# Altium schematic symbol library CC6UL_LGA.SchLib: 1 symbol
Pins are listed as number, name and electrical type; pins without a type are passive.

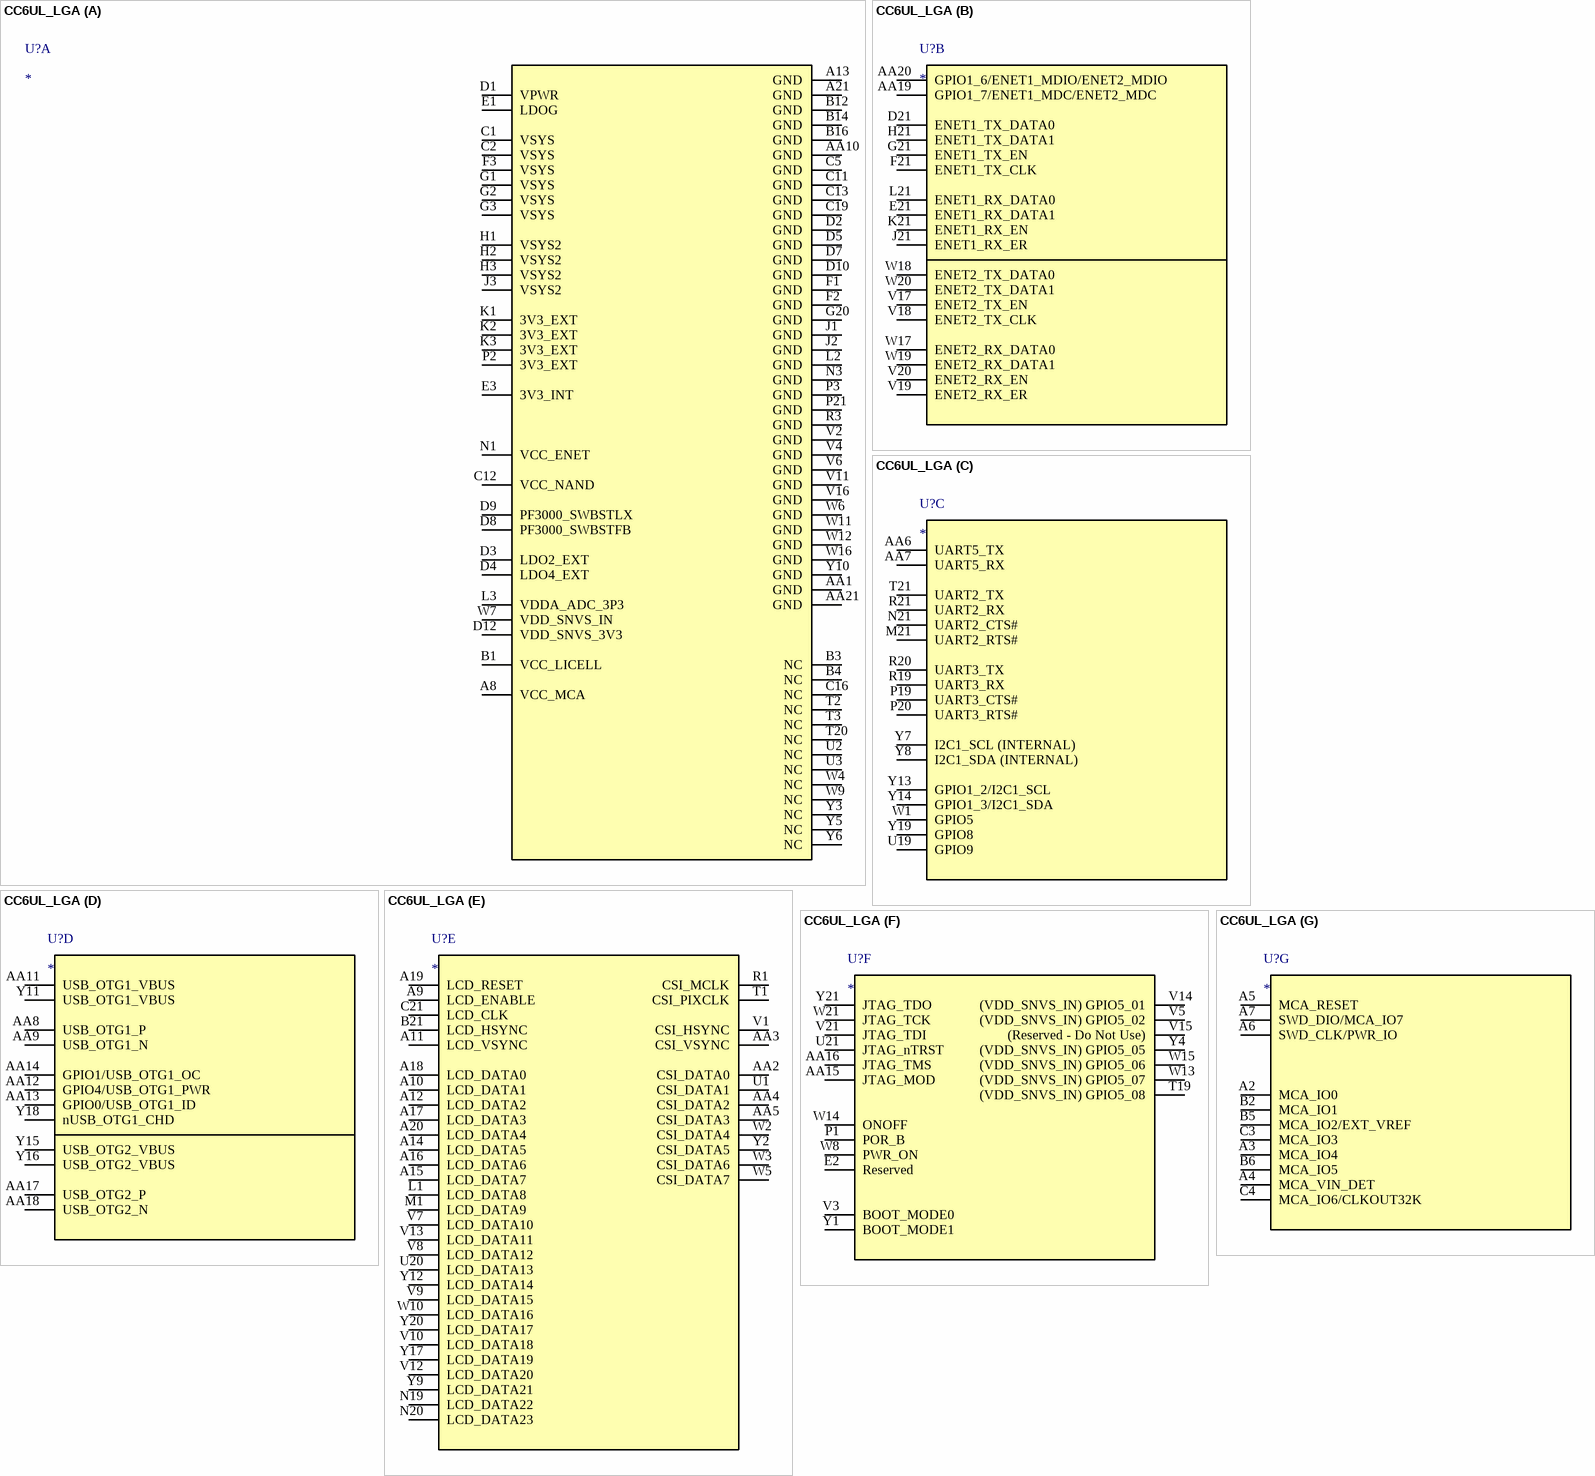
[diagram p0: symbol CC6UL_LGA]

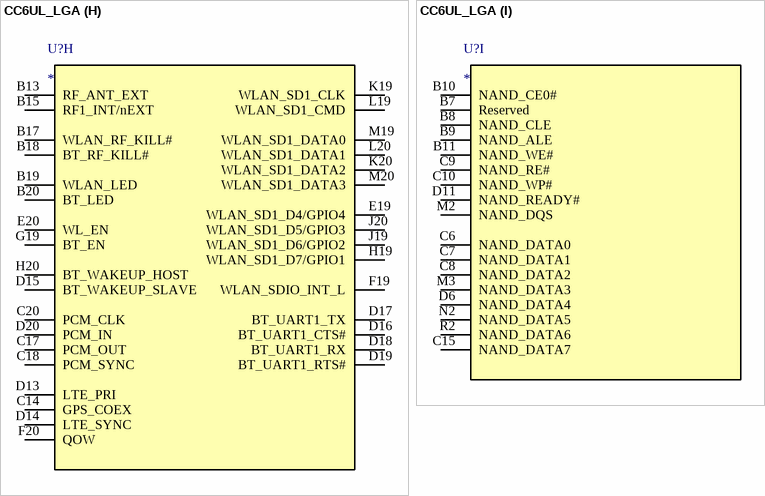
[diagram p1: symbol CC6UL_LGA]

## CC6UL_LGA
designator U?
CC6UL LGA
part A pins: A8 VCC_MCA (power), A13 GND (power), A21 GND, AA1 GND, AA10 GND (power), AA21 GND, B1 VCC_LICELL, B3 NC, B4 NC, B12 GND, B14 GND, B16 GND, C1 VSYS, C2 VSYS, C5 GND, C11 GND, C12 VCC_NAND, C13 GND, C16 NC, C19 GND, D1 VPWR, D2 GND, D3 LDO2_EXT, D4 LDO4_EXT, D5 GND, D7 GND, D8 PF3000_SWBSTFB, D9 PF3000_SWBSTLX, D10 GND, D12 VDD_SNVS_3V3, E1 LDOG, E3 3V3_INT, F1 GND (power), F2 GND, F3 VSYS, G1 VSYS (power), G2 VSYS, G3 VSYS, G20 GND, H1 VSYS2 (power), H2 VSYS2, H3 VSYS2, J1 GND (power), J2 GND, J3 VSYS2, K1 3V3_EXT (power), K2 3V3_EXT, K3 3V3_EXT, L2 GND, L3 VDDA_ADC_3P3, N1 VCC_ENET (power), N3 GND, P2 3V3_EXT, P3 GND, P21 GND, R3 GND, T2 NC, T3 NC, T20 NC, U2 NC, U3 NC, V2 GND, V4 GND, V6 GND, V11 GND, V16 GND, W4 NC, W6 GND, W7 VDD_SNVS_IN, W9 NC, W11 GND, W12 GND, W16 GND, Y3 NC, Y5 NC, Y6 NC, Y10 GND
part B pins: AA19 GPIO1_7/ENET1_MDC/ENET2_MDC, AA20 GPIO1_6/ENET1_MDIO/ENET2_MDIO, D21 ENET1_TX_DATA0, E21 ENET1_RX_DATA1, F21 ENET1_TX_CLK, G21 ENET1_TX_EN, H21 ENET1_TX_DATA1, J21 ENET1_RX_ER, K21 ENET1_RX_EN, L21 ENET1_RX_DATA0, V17 ENET2_TX_EN, V18 ENET2_TX_CLK, V19 ENET2_RX_ER, V20 ENET2_RX_EN, W17 ENET2_RX_DATA0, W18 ENET2_TX_DATA0, W19 ENET2_RX_DATA1, W20 ENET2_TX_DATA1
part C pins: AA6 UART5_TX, AA7 UART5_RX, M21 UART2_RTS#, N21 UART2_CTS#, P19 UART3_CTS#, P20 UART3_RTS#, R19 UART3_RX, R20 UART3_TX, R21 UART2_RX, T21 UART2_TX, U19 GPIO9, W1 GPIO5, Y7 I2C1_SCL (INTERNAL), Y8 I2C1_SDA (INTERNAL), Y13 GPIO1_2/I2C1_SCL, Y14 GPIO1_3/I2C1_SDA, Y19 GPIO8
part D pins: AA8 USB_OTG1_P, AA9 USB_OTG1_N, AA11 USB_OTG1_VBUS, AA12 GPIO4/USB_OTG1_PWR, AA13 GPIO0/USB_OTG1_ID, AA14 GPIO1/USB_OTG1_OC, AA17 USB_OTG2_P, AA18 USB_OTG2_N, Y11 USB_OTG1_VBUS, Y15 USB_OTG2_VBUS, Y16 USB_OTG2_VBUS, Y18 nUSB_OTG1_CHD
part E pins: A9 LCD_ENABLE, A10 LCD_DATA1, A11 LCD_VSYNC, A12 LCD_DATA2, A14 LCD_DATA5, A15 LCD_DATA7, A16 LCD_DATA6, A17 LCD_DATA3, A18 LCD_DATA0, A19 LCD_RESET, A20 LCD_DATA4, AA2 CSI_DATA0, AA3 CSI_VSYNC, AA4 CSI_DATA2, AA5 CSI_DATA3, B21 LCD_HSYNC, C21 LCD_CLK, L1 LCD_DATA8, M1 LCD_DATA9, N19 LCD_DATA22, N20 LCD_DATA23, R1 CSI_MCLK, T1 CSI_PIXCLK, U1 CSI_DATA1, U20 LCD_DATA13, V1 CSI_HSYNC, V7 LCD_DATA10, V8 LCD_DATA12, V9 LCD_DATA15, V10 LCD_DATA18, V12 LCD_DATA20, V13 LCD_DATA11, W2 CSI_DATA4, W3 CSI_DATA6, W5 CSI_DATA7, W10 LCD_DATA16, Y2 CSI_DATA5, Y9 LCD_DATA21, Y12 LCD_DATA14, Y17 LCD_DATA19, Y20 LCD_DATA17
part F pins: AA15 JTAG_MOD, AA16 JTAG_TMS, E2 Reserved, P1 POR_B, T19 (VDD_SNVS_IN) GPIO5_08, U21 JTAG_nTRST, V3 BOOT_MODE0, V5 (VDD_SNVS_IN) GPIO5_02, V14 (VDD_SNVS_IN) GPIO5_01, V15 (Reserved - Do Not Use), V21 JTAG_TDI, W8 PWR_ON, W13 (VDD_SNVS_IN) GPIO5_07, W14 ONOFF, W15 (VDD_SNVS_IN) GPIO5_06, W21 JTAG_TCK, Y1 BOOT_MODE1, Y4 (VDD_SNVS_IN) GPIO5_05, Y21 JTAG_TDO
part G pins: A2 MCA_IO0, A3 MCA_IO4, A4 MCA_VIN_DET, A5 MCA_RESET, A6 SWD_CLK/PWR_IO, A7 SWD_DIO/MCA_IO7, B2 MCA_IO1, B5 MCA_IO2/EXT_VREF, B6 MCA_IO5, C3 MCA_IO3, C4 MCA_IO6/CLKOUT32K
part H pins: B13 RF_ANT_EXT, B15 RF1_INT/nEXT, B17 WLAN_RF_KILL#, B18 BT_RF_KILL#, B19 WLAN_LED, B20 BT_LED, C14 GPS_COEX, C17 PCM_OUT, C18 PCM_SYNC, C20 PCM_CLK, D13 LTE_PRI, D14 LTE_SYNC, D15 BT_WAKEUP_SLAVE, D16 BT_UART1_CTS#, D17 BT_UART1_TX, D18 BT_UART1_RX, D19 BT_UART1_RTS#, D20 PCM_IN, E19 WLAN_SD1_D4/GPIO4, E20 WL_EN, F19 WLAN_SDIO_INT_L, F20 QOW, G19 BT_EN, H19 WLAN_SD1_D7/GPIO1, H20 BT_WAKEUP_HOST, J19 WLAN_SD1_D6/GPIO2, J20 WLAN_SD1_D5/GPIO3, K19 WLAN_SD1_CLK, K20 WLAN_SD1_DATA2, L19 WLAN_SD1_CMD, L20 WLAN_SD1_DATA1, M19 WLAN_SD1_DATA0, M20 WLAN_SD1_DATA3
part I pins: B7 Reserved, B8 NAND_CLE, B9 NAND_ALE, B10 NAND_CE0#, B11 NAND_WE#, C6 NAND_DATA0, C7 NAND_DATA1, C8 NAND_DATA2, C9 NAND_RE#, C10 NAND_WP#, C15 NAND_DATA7, D6 NAND_DATA4, D11 NAND_READY#, M2 NAND_DQS, M3 NAND_DATA3, N2 NAND_DATA5, R2 NAND_DATA6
